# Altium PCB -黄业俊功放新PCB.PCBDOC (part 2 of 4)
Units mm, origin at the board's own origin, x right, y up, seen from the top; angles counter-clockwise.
Board outline 130 x 100.6 mm, 2 copper layers (Top Layer, Bottom Layer); 47 components, 24 nets, 117 pads, 4 vias.
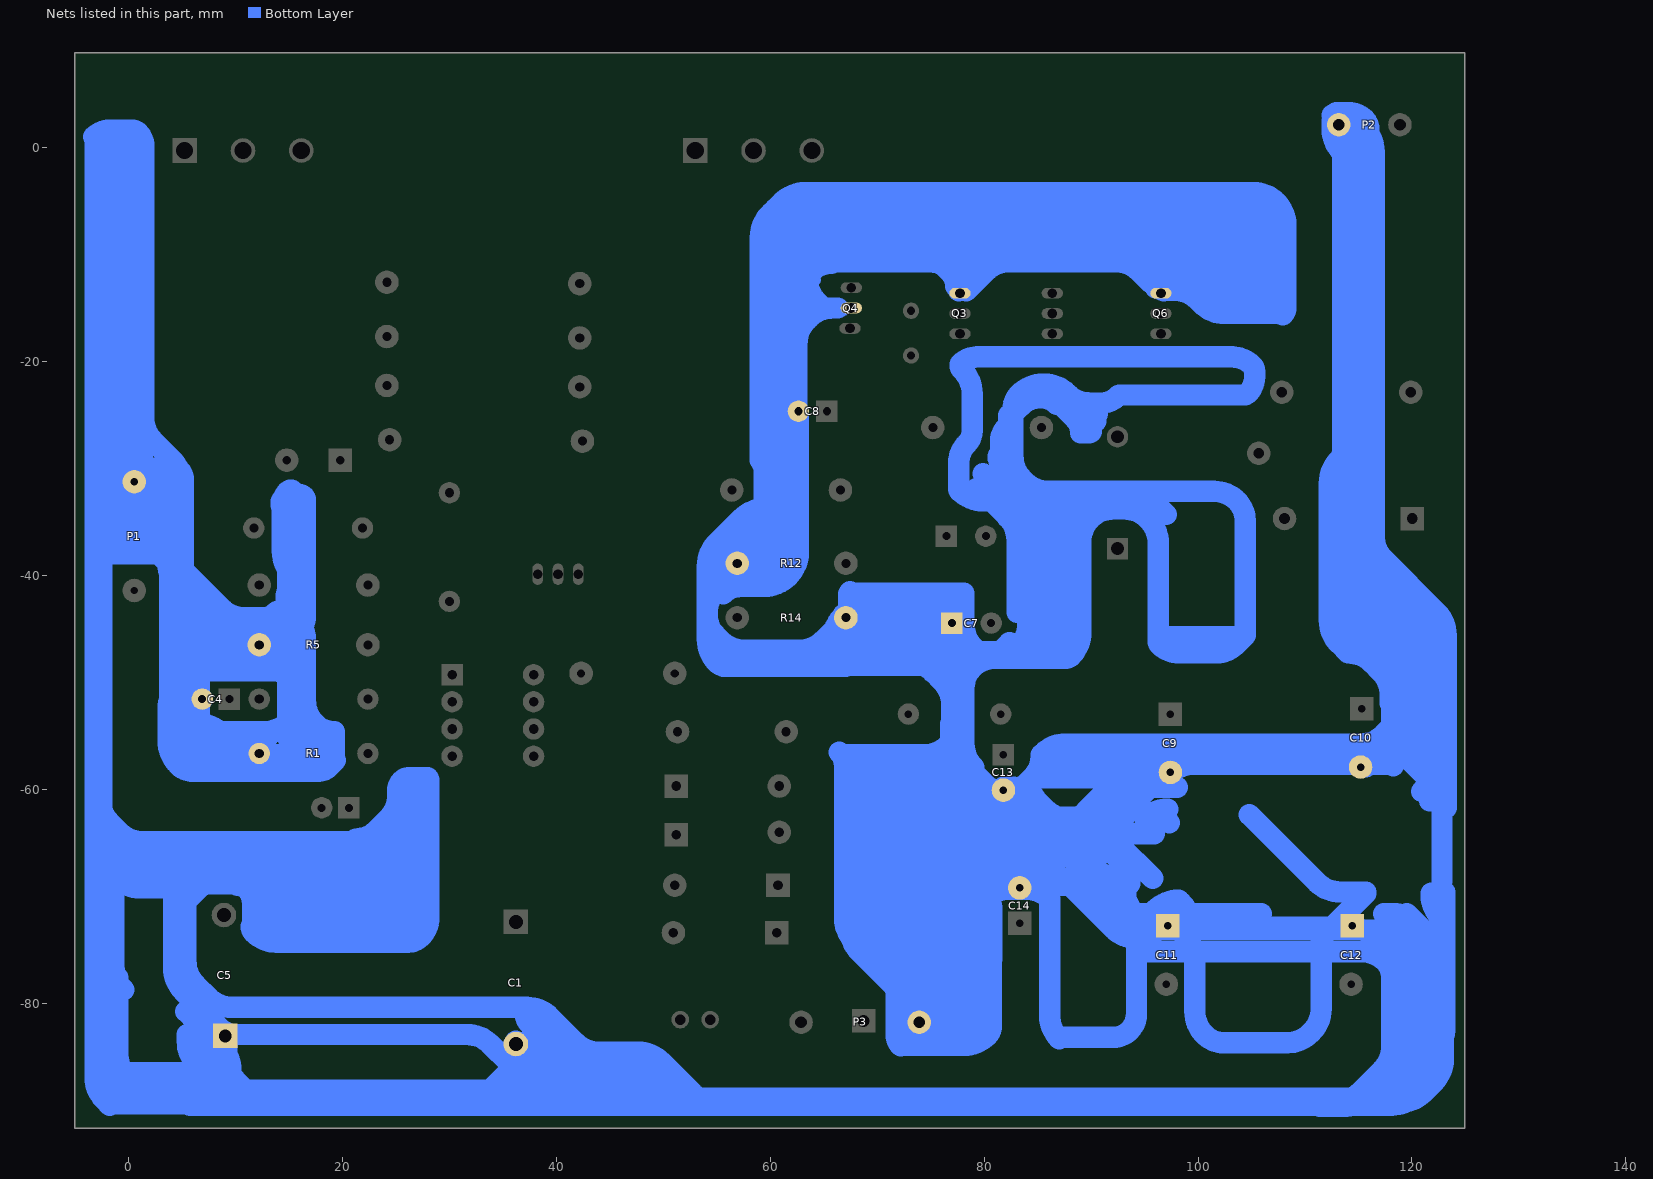
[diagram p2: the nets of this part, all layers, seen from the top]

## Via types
v1: diameter 2.54, hole 0.762, Top Layer to Bottom Layer, 4 vias

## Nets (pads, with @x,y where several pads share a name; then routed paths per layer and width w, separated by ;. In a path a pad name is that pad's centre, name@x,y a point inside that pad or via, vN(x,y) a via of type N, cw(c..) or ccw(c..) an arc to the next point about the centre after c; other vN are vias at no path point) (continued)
GND: (continued)
  Bottom Layer w2: -2.667,-58.42 -2.667,-60.96 ccw(c0.399,-60.96) -1.769,-63.128 -0.898,-63.999 ccw(c1.27,-61.831) 1.27,-64.897 24.892,-64.897 cw(c24.892,-67.963) 27.06,-65.795 cw(c25.549,-67.306) 27.686,-67.306 27.686,-71.628 cw(c24.62,-71.628) 26.788,-73.796 cw(c25.583,-72.591) 25.583,-74.295 13.843,-74.295 cw(c13.843,-71.229) 11.675,-73.397 cw(c12.266,-72.806) 11.43,-72.806 ccw(c11.43,-72.582) 11.588,-72.74 ccw(c10.742,-71.895) 11.938,-71.895 11.938,-70.367 ccw(c9.77,-70.367) 11.303,-68.834 7.682,-68.834 ccw(c7.682,-71.436) 5.842,-69.596 ccw(c7.068,-70.822) 5.334,-70.822 5.334,-76.073 ccw(c8.4,-76.073) 6.232,-78.241 7.484,-79.493 ccw(c9.652,-77.325) 9.652,-80.391 37.211,-80.391 cw(c37.211,-83.457) 39.379,-81.289 41.774,-83.684 ccw(c43.942,-81.516) 43.942,-84.582 47.625,-84.582 cw(c47.625,-87.648) 49.793,-85.48 52.696,-88.383 ccw(c54.864,-86.215) 54.864,-89.281 61.087,-89.281 ; -2.667,-39.624 -2.667,-32.233 cw(c-1.549,-32.233) -1.549,-31.115 P1.1@0.381,-31.115 ; -2.54,-51.816 -2.54,-33.831 ; -2.54,-47.244 -2.54,-88.29 ccw(c-1.422,-88.29) -1.422,-89.408 11.303,-89.408 ; -2.413,-80.391 -2.413,-85.623 ccw(c0.285,-85.623) -1.623,-87.531 -0.536,-88.618 ccw(c1.372,-86.71) 1.372,-89.408 8.382,-89.408 ; -2.413,-78.613 -2.413,-83.845 ccw(c0.285,-83.845) -1.623,-85.753 -0.028,-87.348 ccw(c1.88,-85.44) 1.88,-88.138 35.814,-88.138 ; -2.159,-64.516 -1.152,-65.523 ccw(c1.016,-63.355) 1.016,-66.421 24.003,-66.421 cw(c24.003,-69.487) 26.171,-67.319 ccw(c26.193,-67.341) 26.162,-67.341 26.162,-71.374 cw(c23.096,-71.374) 25.264,-73.542 ccw(c23.709,-75.097) 23.709,-72.898 14.794,-72.898 cw(c14.794,-70.296) 12.954,-72.136 cw(c13.261,-71.829) 12.827,-71.829 12.827,-70.358 ccw(c9.761,-70.358) 11.929,-68.19 ccw(c11.644,-68.475) 11.644,-68.072 1.143,-68.072 cw(c1.143,-65.006) -1.025,-67.174 -2.286,-65.913 ccw(c0.78,-65.913) -1.388,-68.081 -1.152,-68.317 ccw(c1.016,-66.149) 1.016,-69.215 5.588,-69.215 ; -1.905,0.762 -1.905,-30.703 ccw(c-0.604,-30.703) -1.524,-31.623 ; -1.778,-89.535 -2.277,-89.036 cw(c-0.109,-86.868) -3.175,-86.868 -3.175,0.709 ccw(c-3.609,0.709) -3.302,1.016 cw(c-1.769,-0.517) -1.769,1.651 0.276,1.651 cw(c0.276,0.784) 0.889,1.397 cw(c-0.337,0.171) 1.397,0.171 1.397,-25.273 ccw(c4.463,-25.273) 2.295,-27.441 4.07,-29.216 cw(c2.553,-30.734) 4.699,-30.734 ; -1.651,-1.524 -0.396,-0.269 ccw(c-1.047,0.381) -0.127,0.381 -0.127,-6.043 cw(c-0.561,-6.043) -0.254,-6.35 cw(c-0.561,-6.657) -0.127,-6.657 -0.127,-31.242 0.372,-30.743 ccw(c-1.796,-28.575) 1.27,-28.575 1.27,-27.283 ccw(c0.403,-27.283) 1.016,-26.67 ; -1.524,-37.211 1.168,-37.211 cw(c1.168,-39.909) 3.076,-38.001 3.274,-38.199 cw(c1.366,-40.107) 4.064,-40.107 4.064,-43.688 ; -1.397,-69.215 -1.397,-76.581 ccw(c1.669,-76.581) -0.499,-78.749 ; -1.016,-77.597 -1.016,-84.954 ccw(c1.152,-84.954) -0.381,-86.487 7.992,-86.487 cw(c7.992,-88.655) 9.525,-87.122 9.525,-86.233 ccw(c6.459,-86.233) 8.627,-84.065 5.334,-80.772 6.214,-81.652 cw(c4.046,-83.82) 7.112,-83.82 7.112,-86.487 6.359,-85.734 cw(c8.527,-83.566) 5.461,-83.566 5.461,-82.931 31.623,-82.931 cw(c31.623,-85.997) 33.791,-83.829 35.56,-85.598 ; 0.254,-30.099 2.741,-30.099 ccw(c2.741,-29.665) 3.048,-29.972 cw(c1.515,-31.505) 3.683,-31.505 3.683,-39.014 ccw(c6.381,-39.014) 4.473,-40.922 8.481,-44.93 ccw(c10.389,-43.022) 10.389,-45.72 R5.1@11.938,-45.72 ; 0.381,-36.322 ccw(c1.607,-35.096) 1.607,-36.83 1.651,-36.83 2.704,-37.883 ccw(c2.921,-37.666) 2.921,-37.973 ccw(c3.228,-37.973) 3.011,-38.19 3.959,-39.138 cw(c3.092,-40.005) 4.318,-40.005 ccw(c5.544,-40.005) 4.677,-40.872 4.699,-40.894 4.699,-42.164 cw(c4.392,-42.471) 4.826,-42.471 4.826,-53.492 ccw(c7.524,-53.492) 5.616,-55.4 6.068,-55.852 ccw(c7.976,-53.944) 7.976,-56.642 12.065,-56.642 8.738,-56.642 cw(c8.738,-53.944) 6.83,-55.852 cw(c7.681,-55) 6.477,-55 ; 0.635,-33.581 ccw(c0.201,-33.581) 0.508,-33.274 0.508,-34.491 ccw(c0.942,-34.491) 0.635,-34.798 ccw(c2.168,-36.331) 0,-36.331 0,-36.703 ccw(c0,-37.601) -0.635,-36.966 -0.694,-37.025 ccw(c-1.524,-37.855) -1.524,-36.681 cw(c-0.657,-36.681) -1.27,-36.068 ccw(c-2.496,-34.842) -0.762,-34.842 -0.762,-34.544 cw(c0.464,-34.544) -0.403,-33.677 1.143,-32.131 cw(c0.223,-33.051) 1.524,-33.051 1.524,-33.931 ccw(c2.391,-33.931) 1.778,-34.544 1.778,-35.941 cw(c1.778,-35.836) 1.704,-35.91 1.121,-35.328 cw(c0.635,-34.842) 0.635,-35.529 cw(c-0.285,-35.529) 0.366,-36.18 cw(c-0.285,-36.83) 0.635,-36.83 cw(c0.635,-38.67) 1.936,-37.369 2.286,-37.719 ccw(c0.446,-35.879) 3.048,-35.879 3.048,-31.242 ccw(c2.741,-31.549) 2.741,-31.115 1.118,-31.115 ccw(c1.118,-33.813) -0.79,-31.905 -1.496,-32.611 ccw(c0.412,-34.519) -2.286,-34.519 -2.286,-37.973 2.184,-37.973 cw(c2.184,-40.671) 4.092,-38.763 ; 2.413,-29.972 4.392,-29.972 cw(c4.392,-30.406) 4.699,-30.099 cw(c3.779,-31.019) 5.08,-31.019 5.08,-41.529 ; 2.54,-35.814 2.54,-35.839 ccw(c5.238,-35.839) 3.33,-37.747 ; 3.81,-50.038 3.81,-55.827 ccw(c4.244,-55.827) 3.937,-56.134 ccw(c5.47,-54.601) 5.47,-56.769 R1.2@11.684,-56.769 ; 3.81,-39.624 3.81,-53.111 ccw(c6.508,-53.111) 4.6,-55.019 5.56,-55.979 ccw(c7.468,-54.071) 7.468,-56.769 R1.2@12.065,-56.769 ; 4.191,-69.977 4.191,-76.708 ccw(c7.257,-76.708) 5.089,-78.876 C5.1@8.763,-82.55 ; 4.318,-35.56 4.318,-37.465 ccw(c7.384,-37.465) 5.216,-39.633 8.627,-43.044 ccw(c10.795,-40.876) 10.795,-43.942 14.649,-43.942 cw(c14.649,-45.676) 15.875,-44.45 cw(c14.342,-45.983) 16.51,-45.983 16.51,-51.689 ccw(c19.576,-51.689) 17.408,-53.857 ccw(c19.226,-52.039) 19.226,-54.61 19.226,-57.088 ccw(c19.493,-57.088) 19.304,-57.277 18.647,-57.934 cw(c17.78,-57.067) 17.78,-58.293 5.842,-58.293 cw(c5.842,-56.76) 4.758,-57.844 4.581,-57.667 cw(c6.749,-55.499) 3.683,-55.499 3.683,-54.356 3.683,-52.451 cw(c6.749,-52.451) 4.581,-50.283 5.452,-49.412 cw(c7.62,-51.58) 7.62,-48.514 12.967,-48.514 cw(c12.967,-51.549) 15.113,-49.403 cw(c14.193,-50.323) 15.494,-50.323 15.494,-52.451 ccw(c18.56,-52.451) 16.392,-54.619 17.653,-55.88 17.653,-56.178 cw(c15.919,-56.178) 17.145,-57.404 14.741,-57.404 cw(c14.741,-55.236) 13.208,-56.769 15.717,-56.769 ccw(c15.717,-55.468) 16.637,-56.388 cw(c16.944,-56.081) 16.51,-56.081 cw(c16.51,-54.421) 15.336,-55.595 14.097,-54.356 ccw(c14.097,-55.582) 13.23,-54.715 13.171,-54.774 ccw(c13.388,-54.991) 13.081,-54.991 12.88,-54.991 ccw(c12.88,-55.425) 12.573,-55.118 ccw(c12.266,-55.425) 12.266,-54.991 8.487,-54.991 cw(c8.487,-54.124) 7.874,-54.737 7.614,-54.477 ccw(c6.096,-55.994) 6.096,-53.848 6.477,-53.848 cw(c6.477,-56.914) 8.645,-54.746 cw(c8.973,-55.074) 8.973,-54.61 12.7,-54.61 ccw(c12.7,-51.544) 14.868,-53.712 cw(c14.89,-53.69) 14.859,-53.69 14.859,-49.71 ccw(c14.425,-49.71) 14.732,-49.403 ccw(c13.506,-50.629) 13.506,-48.895 7.8,-48.895 cw(c7.8,-48.461) 7.493,-48.768 7.738,-48.523 cw(c9.906,-50.691) 9.906,-47.625 14.447,-47.625 cw(c14.447,-48.926) 15.367,-48.006 ccw(c15.06,-47.699) 15.494,-47.699 15.494,-45.974 15.076,-45.556 ccw(c14.859,-45.773) 14.859,-45.466 13.896,-45.466 cw(c13.896,-45.032) 13.589,-45.339 cw(c11.443,-43.193) 11.443,-46.228 11.96,-46.228 cw(c11.96,-47.095) 12.573,-46.482 cw(c12.88,-46.789) 12.88,-46.355 14.933,-46.355 ccw(c14.933,-45.921) 15.24,-46.228 15.612,-45.856 ccw(c13.444,-43.688) 16.51,-43.688 16.51,-38.354 16.51,-33.782 16.51,-32.946 ccw(c16.076,-32.946) 16.383,-32.639 ccw(c15.77,-33.252) 15.77,-32.385 15.547,-32.385 ccw(c15.547,-32.819) 15.24,-32.512 cw(c14.933,-32.205) 14.933,-32.639 ccw(c14.933,-33.432) 14.373,-32.871 ccw(c14.732,-33.23) 14.224,-33.23 ccw(c14.942,-33.23) 14.434,-33.738 cw(c14.023,-34.15) 14.605,-34.15 14.605,-35.306 14.605,-36.904 ccw(c15.039,-36.904) 14.732,-37.211 14.732,-39.063 ccw(c15.166,-39.063) 14.859,-39.37 14.859,-41.529 ccw(c15.166,-41.836) 14.732,-41.836 14.732,-42.26 cw(c13.431,-42.26) 14.351,-43.18 14.224,-43.307 14.202,-43.307 ccw(c14.202,-44.174) 13.589,-43.561 cw(c12.669,-42.641) 12.669,-43.942 11.303,-43.942 7.905,-43.942 cw(c7.905,-42.641) 6.985,-43.561 6.709,-43.285 ccw(c5.842,-44.152) 5.842,-42.926 ; 4.346,-39.144 cw(c6.254,-37.236) 3.556,-37.236 3.556,-32.106 ccw(c0.858,-32.106) 2.766,-30.198 ccw(c2.221,-30.743) 2.221,-29.972 -1.927,-29.972 ccw(c-1.927,-30.839) -2.54,-30.226 ccw(c-1.927,-30.839) -2.794,-30.839 -2.794,-83.845 ccw(c-0.096,-83.845) -2.004,-85.753 0.099,-87.856 ccw(c2.007,-85.948) 2.007,-88.646 36.269,-88.646 ccw(c36.269,-88.212) 36.576,-88.519 ccw(c37.496,-87.599) 37.496,-88.9 118.262,-88.9 ccw(c118.262,-86.202) 120.17,-88.11 121.613,-86.667 ccw(c121.18,-86.233) 121.793,-86.233 121.793,-84.762 cw(c122.227,-84.762) 121.92,-84.455 121.92,-80.317 cw(c122.354,-80.317) 122.047,-80.01 122.047,-76.835 122.047,-75.057 122.047,-73.533 122.047,-83.337 cw(c119.349,-83.337) 121.257,-85.245 117.602,-88.9 ; 4.572,-70.739 ccw(c4.572,-69.513) 5.439,-70.38 9.017,-66.802 ; 4.572,-51.562 C4.2@6.858,-51.562 ; 4.572,-50.292 7.084,-47.78 ; 4.826,-53.34 ccw(c5.439,-53.34) 5.006,-53.774 6.068,-54.836 ccw(c7.976,-52.928) 7.976,-55.626 8.636,-55.626 ; 4.826,-50.673 6.551,-48.948 cw(c6.985,-49.381) 6.985,-48.768 ; 4.953,-46.228 R5.1@12.065,-46.228 ; 5.588,-89.408 7.899,-89.408 ccw(c7.899,-88.29) 9.017,-88.29 C5.1@9.017,-82.677 ; 5.588,-50.673 5.588,-51.714 ccw(c8.286,-51.714) 6.378,-53.622 8.227,-55.471 ccw(c10.135,-53.563) 10.135,-56.261 R1.2@11.938,-56.261 ; 5.588,-44.323 cw(c5.588,-44.63) 5.805,-44.413 6.195,-44.803 ccw(c8.103,-42.895) 8.103,-45.593 8.509,-45.593 ; 5.588,-42.418 8.608,-45.438 ccw(c10.516,-43.53) 10.516,-46.228 R5.1@11.811,-46.228 ; 5.715,-89.535 118.11,-89.535 ccw(c118.11,-86.469) 120.278,-88.637 121.403,-87.512 ccw(c119.235,-85.344) 122.301,-85.344 122.301,-74.23 cw(c124.903,-74.23) 123.063,-72.39 122.691,-72.018 cw(c124.859,-69.85) 121.793,-69.85 121.793,-69.723 ; 5.969,-88.646 8.227,-86.388 ccw(c6.319,-84.48) 9.017,-84.48 C5.1@9.017,-82.804 ; C4.2@5.969,-51.308 cw(c4.436,-52.841) 6.604,-52.841 6.604,-53.594 7.846,-54.836 ccw(c9.754,-52.928) 9.754,-55.626 11.43,-55.626 ; 6.604,-89.408 8.227,-87.785 ccw(c6.319,-85.877) 9.017,-85.877 C5.1@9.017,-83.185 ; 6.604,-55.403 cw(c6.508,-55.403) 6.576,-55.471 ccw(c8.484,-53.563) 8.484,-56.261 R1.2@11.811,-56.261 ; C4.2@6.604,-51.562 6.604,-54.811 ccw(c7.038,-54.811) 6.731,-55.118 ; C4.2@6.604,-51.308 6.604,-48.567 cw(c7.038,-48.567) 6.731,-48.26 ; 6.716,-47.386 ccw(c6.065,-46.736) 6.985,-46.736 ; 6.731,-55.143 ccw(c7.849,-55.143) 7.849,-56.261 R1.2@12.065,-56.261 ; 6.731,-48.768 6.731,-48.895 8.735,-46.891 cw(c10.643,-48.799) 10.643,-46.101 R5.1@11.684,-46.101 ; C5.1@9.017,-83.312 9.017,-85.75 ccw(c11.715,-85.75) 9.807,-87.658 11.684,-89.535 ; C5.1@9.144,-82.804 9.144,-85.242 ccw(c11.842,-85.242) 9.934,-87.15 11.594,-88.81 ccw(c11.811,-88.593) 11.811,-88.9 ; 10.16,-68.961 cw(c10.16,-70.187) 11.027,-69.32 cw(c9.748,-70.599) 11.557,-70.599 11.557,-72.39 ; R1.2@12.192,-56.769 R1.2@12.192,-55.753 ; 12.573,-68.072 24.301,-68.072 cw(c24.301,-69.806) 25.527,-68.58 25.527,-69.915 cw(c22.925,-69.915) 24.765,-71.755 15.757,-71.755 cw(c15.757,-69.587) 14.224,-71.12 14.224,-69.903 ccw(c13.79,-69.903) 14.097,-69.596 14.224,-69.469 14.605,-69.469 ccw(c16.138,-67.936) 16.138,-70.104 24.511,-70.104 23.832,-70.104 ccw(c23.832,-71.838) 22.606,-70.612 cw(c21.686,-69.692) 21.686,-70.993 ; 15.24,-43.561 15.24,-39.909 cw(c15.271,-39.909) 15.249,-39.887 cw(c17.417,-37.719) 14.351,-37.719 14.351,-33.283 cw(c15.906,-33.283) 14.806,-32.184 cw(c15.24,-32.617) 15.24,-32.004 ; 21.209,-64.643 ccw(c21.209,-61.884) 23.16,-63.835 24.248,-62.747 ccw(c22.08,-60.579) 25.146,-60.579 25.146,-60.102 cw(c26.447,-60.102) 25.527,-59.182 cw(c26.14,-59.795) 26.14,-58.928 27.94,-58.928 cw(c27.633,-59.235) 28.067,-59.235 28.067,-71.947 cw(c25.465,-71.947) 27.305,-73.787 cw(c26.079,-72.561) 26.079,-74.295 23.876,-74.295 cw(c23.876,-71.229) 21.708,-73.397 21.494,-73.183 cw(c22.795,-71.882) 20.955,-71.882 20.955,-68.961 cw(c24.021,-68.961) 21.853,-66.793 25.772,-62.874 ccw(c23.604,-60.706) 26.67,-60.706 26.67,-60.452 26.67,-62.834 ccw(c27.971,-62.834) 27.051,-63.754 26.76,-64.045 ccw(c26.977,-64.262) 26.67,-64.262 26.67,-64.389 ; 33.02,-88.9 35.151,-86.769 ccw(c33.243,-84.861) 35.941,-84.861 C1.2@35.941,-83.947 ; C1.2@36.195,-83.82 36.195,-89.228 ccw(c36.629,-89.228) 36.322,-89.535 ; C1.2@36.195,-83.566 36.195,-84.861 ccw(c38.893,-84.861) 36.985,-86.769 39.243,-89.027 ; 37.084,-81.026 ccw(c38.31,-81.026) 37.443,-81.893 40.885,-85.335 ccw(c43.053,-83.167) 43.053,-86.233 47.752,-86.233 cw(c47.752,-89.299) 49.92,-87.131 50.673,-87.884 42.799,-87.884 cw(c42.799,-84.818) 40.631,-86.986 37.211,-83.566 38.345,-84.7 cw(c36.177,-86.868) 39.243,-86.868 39.243,-88.646 38.363,-87.766 cw(c40.531,-85.598) 37.465,-85.598 ; 54.102,-45.085 ccw(c57.168,-45.085) 55,-47.253 55.109,-47.362 ccw(c57.277,-45.194) 57.277,-48.26 63.574,-48.26 ccw(c63.574,-47.826) 63.881,-48.133 cw(c64.494,-48.746) 64.494,-47.879 67.078,-47.879 ccw(c67.078,-47.012) 67.691,-47.625 ; 54.102,-44.704 54.102,-43.434 cw(c57.168,-43.434) 55,-41.266 55.109,-41.157 cw(c57.277,-43.325) 57.277,-40.259 60.307,-40.259 ccw(c60.307,-38.989) 61.205,-39.887 ccw(c59.037,-37.719) 62.103,-37.719 62.103,-31.877 ; 54.102,-43.815 ccw(c56.555,-43.815) 54.82,-45.549 55.363,-46.092 ccw(c57.531,-43.924) 57.531,-46.99 62.738,-46.99 ccw(c62.738,-43.924) 64.906,-46.092 66.793,-44.205 cw(c68.961,-46.373) 68.961,-43.307 75.587,-43.307 cw(c75.587,-44.174) 76.2,-43.561 cw(c75.893,-43.868) 76.327,-43.868 C7.1@76.327,-45.339 ; 54.102,-42.291 cw(c57.168,-42.291) 55,-40.123 55.722,-39.401 cw(c57.023,-40.702) R12.2@57.023,-38.862 ; 54.102,-41.91 54.102,-39.116 cw(c57.168,-39.116) 55,-36.948 57.268,-34.68 cw(c59.436,-36.848) 59.436,-33.782 59.436,-30.13 ccw(c58.135,-30.13) 59.055,-29.21 59.055,-19.641 cw(c60.789,-19.641) 59.563,-18.415 ; 54.229,-39.37 ccw(c54.536,-39.677) 54.102,-39.677 54.102,-45.987 ccw(c57.137,-45.987) 54.991,-48.133 ccw(c55.911,-47.213) 55.911,-48.514 67.056,-48.514 ; 54.414,-39.205 cw(c55.762,-40.903) 54.936,-38.899 cw(c55.762,-40.903) 55.762,-38.735 R12.2@56.007,-38.735 ; 55.245,-38.862 59.458,-34.649 ccw(c58.591,-33.782) 59.817,-33.782 ccw(c58.284,-32.249) 60.452,-32.249 60.452,-31.821 ccw(c58.748,-31.821) 59.953,-30.616 cw(c62.121,-28.448) 59.055,-28.448 59.055,-28.321 59.055,-8.382 cw(c62.121,-8.382) 59.953,-6.214 60.452,-5.715 ; 55.372,-41.145 ccw(c56.142,-41.145) 55.598,-41.689 cw(c57.211,-43.303) 57.211,-41.021 59.436,-41.021 ccw(c59.436,-37.955) 61.604,-40.123 61.713,-40.014 ccw(c59.545,-37.846) 62.611,-37.846 C8.2@62.611,-24.638 ; 55.753,-38.862 56.515,-38.862 ccw(c56.515,-35.796) 57.388,-38.735 ccw(c56.515,-35.796) 58.683,-37.964 60.316,-36.331 ccw(c58.148,-34.163) 61.214,-34.163 61.214,-14.605 ; R12.2@56.388,-38.735 58.674,-38.735 ccw(c58.674,-37.465) 59.856,-37.93 ; R12.2@56.769,-38.862 ccw(c56.769,-35.796) 57.642,-38.735 ccw(c56.769,-35.796) 58.937,-37.964 ccw(c56.813,-35.84) 59.534,-37.113 ccw(c56.813,-35.84) 59.817,-35.84 59.817,-11.049 cw(c62.883,-11.049) 60.071,-9.827 cw(c62.883,-11.049) 60.072,-9.824 ; R12.2@57.785,-38.735 ccw(c57.785,-35.669) 59.856,-37.93 ; 58.293,-48.387 75.946,-48.387 ; 59.182,-8.255 cw(c62.248,-8.255) 60.08,-6.087 61.078,-5.089 cw(c63.246,-7.257) 63.246,-4.191 105.182,-4.191 cw(c105.182,-7.195) 107.306,-5.071 cw(c105.138,-7.239) 108.204,-7.239 108.204,-11.303 ; 59.817,-39.878 60.839,-38.856 ccw(c59.322,-37.338) 61.468,-37.338 ; 59.817,-13.335 59.817,-8.509 cw(c62.883,-8.509) 60.715,-6.341 60.824,-6.232 cw(c62.992,-8.4) 62.992,-5.334 103.251,-5.334 cw(c103.251,-8.4) 105.419,-6.232 107.306,-8.119 cw(c105.138,-10.287) 108.204,-10.287 108.204,-13.282 108.204,-14.953 cw(c107.231,-14.953) 107.919,-15.641 ccw(c107.565,-15.995) 107.565,-15.494 102.489,-15.494 cw(c102.489,-12.428) 100.321,-14.596 99.958,-14.233 ccw(c97.79,-16.401) 97.79,-13.335 97.536,-13.335 cw(c97.536,-10.269) 95.368,-12.437 94.497,-11.566 ccw(c92.329,-13.734) 92.329,-10.668 82.296,-10.668 ccw(c82.296,-13.734) 80.128,-11.566 Q3.1@78.325,-13.369 ; 60.071,-26.67 ccw(c60.071,-26.416) 60.325,-26.416 ; 60.071,-9.902 cw(c62.208,-9.902) 60.072,-9.824 ; 60.288,-11.213 62.221,-9.28 cw(c64.389,-11.448) 62.473,-9.054 ; 61.214,-28.011 cw(c65.984,-28.011) C8.2@62.611,-24.638 ; 61.214,-21.265 ccw(c65.984,-21.265) C8.2@62.611,-24.638 ; 61.214,-16.383 62.162,-15.435 cw(c63.246,-16.519) 62.401,-15.24 cw(c63.246,-16.519) 63.246,-14.986 ; 61.468,-48.514 ccw(c61.468,-45.448) 62.341,-48.387 ccw(c61.468,-45.448) 62.69,-48.26 ccw(c61.468,-45.448) 63.636,-47.616 65.771,-45.481 ccw(c65.12,-44.831) 66.04,-44.831 ; 61.468,-6.985 cw(c63.308,-8.825) 63.308,-6.223 96.012,-6.223 ; 61.595,-16.764 61.595,-17.018 cw(c60.675,-17.938) 61.976,-17.938 61.976,-34.544 cw(c58.91,-34.544) 61.078,-36.712 59.953,-37.837 cw(c57.785,-35.669) 59.856,-37.93 ; 61.864,-10.907 62.602,-10.169 cw(c64.77,-12.337) 64.77,-9.271 ; 61.976,-26.171 cw(c64.144,-26.171) C8.2@62.611,-24.638 ; 61.976,-23.105 ccw(c64.144,-23.105) C8.2@62.611,-24.638 ; 61.976,-14.478 61.976,-13.694 ccw(c61.109,-13.694) 61.722,-13.081 61.722,-11.938 ccw(c62.029,-11.938) 61.812,-12.155 64.516,-14.859 ccw(c64.209,-15.166) 64.209,-14.732 64.135,-14.732 ccw(c62.909,-14.732) 64.101,-14.444 ccw(c62.909,-14.732) 63.776,-13.865 63.5,-13.589 cw(c63.807,-13.282) 63.373,-13.282 63.373,-12.446 cw(c64.599,-12.446) 63.732,-11.579 64.126,-11.185 cw(c66.294,-13.353) 64.555,-10.828 ; 62.103,-17.018 63.5,-15.621 ; C8.2@62.484,-24.257 62.484,-18.288 cw(c65.55,-18.288) 62.57,-17.569 cw(c65.55,-18.288) 63.382,-16.12 63.618,-15.884 cw(c65.786,-18.052) 64.564,-15.24 cw(c65.786,-18.052) 65.786,-14.986 ; 63.106,-7.874 ccw(c63.106,-10.909) 60.96,-8.763 61.512,-8.763 cw(c61.512,-10.497) 62.473,-9.054 ; 63.119,-10.033 76.064,-10.033 cw(c76.064,-12.201) 76.665,-10.118 ; 63.364,-11.566 cw(c65.532,-13.734) 64.555,-10.828 ; 63.364,-11.185 cw(c65.532,-13.353) 64.443,-10.487 cw(c65.532,-13.353) 64.978,-10.337 ; 63.491,-11.312 cw(c65.659,-13.48) 64.075,-10.855 cw(c65.659,-13.48) 65.163,-10.454 ; 63.68,-11.25 64.77,-10.16 ccw(c65.996,-8.934) 64.978,-10.337 ; 63.754,-14.986 66.294,-14.986 ; 63.89,-11.548 cw(c65.708,-13.366) 65.708,-10.795 ; 65.913,-8.382 64.389,-8.382 ccw(c64.389,-11.448) 62.473,-9.054 ; 65.996,-10.668 cw(c65.996,-8.934) 65.216,-10.483 ; 66.167,-46.33 cw(c69.444,-46.33) 67.127,-44.013 cw(c69.137,-46.023) 69.137,-43.18 ; 66.167,-45.292 cw(c67.483,-45.292) R14.2@67.086,-44.037 ; 66.294,-48.387 cw(c66.294,-48.26) 66.167,-48.26 66.167,-44.958 cw(c67.437,-44.958) 67.437,-43.688 74.676,-43.688 cw(c74.676,-44.958) 75.23,-43.815 cw(c74.676,-44.958) 75.946,-44.958 75.946,-45.847 cw(c74.676,-45.847) 75.912,-46.138 ; 66.294,-10.287 ccw(c66.294,-13.353) 65.379,-10.427 ; R14.2@66.802,-43.688 cw(c68.028,-44.914) 68.028,-43.18 77.089,-43.18 cw(c76.782,-43.487) 77.216,-43.487 77.216,-46.736 ; R14.2@66.929,-43.815 75.819,-43.815 ; R14.2@67.31,-43.688 67.31,-41.836 cw(c67.744,-41.836) 67.437,-41.529 ccw(c67.744,-41.222) 67.744,-41.656 78.105,-41.656 78.105,-44.577 ccw(c81.171,-44.577) 79.003,-46.745 79.629,-47.371 ; R14.2@67.437,-44.704 73.787,-44.704 cw(c73.787,-45.339) 74.42,-45.294 ; 68.199,-74.168 cw(c68.199,-74.475) 68.416,-74.258 73.143,-78.985 cw(c70.975,-81.153) 74.041,-81.153 P3.2@74.041,-81.788 ; 68.335,-70.621 cw(c70.503,-68.453) 67.437,-68.453 67.437,-67.31 67.437,-73.025 ccw(c70.503,-73.025) 68.335,-75.193 72.762,-79.62 cw(c70.594,-81.788) P3.2@73.66,-81.788 ; 68.58,-48.133 73.025,-48.133 cw(c73.025,-51.199) 74.247,-48.387 cw(c73.025,-51.199) 75.193,-49.031 76.064,-49.902 cw(c73.896,-52.07) 76.962,-52.07 ; 68.58,-47.117 cw(c68.58,-45.847) 67.564,-46.609 ; 68.961,-10.287 65.532,-10.287 ccw(c65.532,-13.353) 64.978,-10.337 ; 69.088,-74.168 69.596,-74.168 cw(c69.596,-77.234) 71.764,-75.066 73.016,-76.318 cw(c70.848,-78.486) 73.914,-78.486 73.914,-82.169 78.889,-82.169 ccw(c78.889,-81.302) 79.502,-81.915 79.747,-81.67 ccw(c77.579,-79.502) 80.645,-79.502 80.645,-75.565 80.608,-75.528 cw(c80.825,-75.311) 80.518,-75.311 ccw(c80.518,-77.457) 79,-75.94 76.336,-78.604 ccw(c78.504,-80.772) 75.438,-80.772 78.022,-80.772 ccw(c78.022,-79.038) 79.248,-80.264 ccw(c78.022,-79.038) 79.756,-79.038 79.756,-77.965 ccw(c76.721,-77.965) 78.867,-75.819 cw(c77.641,-74.593) 77.641,-76.327 ccw(c77.641,-77.045) 77.133,-76.537 75.147,-78.523 cw(c74.93,-78.306) 74.93,-78.613 74.93,-77.733 ccw(c72.762,-77.733) 74.295,-76.2 cw(c74.602,-76.2) 74.385,-75.983 78.83,-80.428 cw(c78.74,-80.518) 78.867,-80.518 78.867,-78.793 ccw(c78.433,-78.793) 78.74,-78.486 cw(c79.66,-77.566) 78.359,-77.566 78.359,-76.962 77.718,-76.321 cw(c79.235,-74.803) 77.089,-74.803 76.962,-74.803 cw(c76.962,-71.737) 74.794,-73.905 73.019,-72.13 ccw(c71.501,-73.647) 71.501,-71.501 ; 69.137,-44.704 cw(c69.137,-41.861) 67.127,-43.871 ccw(c71.896,-39.102) 71.896,-45.847 ; 70.104,-9.271 74.549,-9.271 cw(c74.549,-12.337) 76.665,-10.118 ; 71.12,-10.414 65.659,-10.414 ccw(c65.659,-13.48) 65.379,-10.427 ; 71.12,-9.525 73.406,-9.525 cw(c73.406,-12.591) 75.043,-9.999 ; 71.247,-77.978 cw(c70.021,-79.204) 71.755,-79.204 71.755,-82.961 ccw(c73.2,-82.961) 72.178,-83.983 cw(c72.265,-84.07) 72.265,-83.947 78.105,-83.947 ccw(c78.105,-80.881) 80.273,-83.049 ccw(c79.375,-82.151) 80.645,-82.151 80.645,-74.676 74.304,-81.017 ccw(c76.472,-83.185) 73.406,-83.185 ; 72.127,-10.668 ccw(c72.127,-8.5) 73.66,-10.033 ; 72.136,-66.802 cw(c72.136,-66.495) 71.919,-66.712 71.628,-66.421 cw(c71.935,-66.114) 71.501,-66.114 71.501,-65.383 ccw(c70.634,-65.383) 71.247,-64.77 ccw(c70.984,-64.507) 71.356,-64.507 71.356,-64.389 cw(c71.356,-65.659) 72.254,-64.761 cw(c70.086,-66.929) 73.152,-66.929 ; 72.263,-44.958 73.025,-44.958 cw(c73.025,-48.024) 74.42,-45.294 ; 73.152,-47.117 ccw(c73.152,-45.847) 74.422,-45.847 74.422,-45.339 ccw(c73.787,-45.339) 74.42,-45.294 ; 73.45,-75.99 72.526,-75.066 ccw(c70.358,-77.234) 70.358,-74.168 67.818,-74.168 cw(c69.964,-72.022) 66.929,-72.022 66.929,-57.741 ccw(c65.195,-57.741) 66.421,-56.515 ccw(c67.034,-55.902) 67.034,-56.769 74.422,-56.769 ccw(c74.422,-53.703) 76.59,-55.871 76.64,-55.821 ccw(c75.556,-54.737) 77.089,-54.737 ; 73.896,-43.18 cw(c73.896,-47.516) C7.1@76.962,-44.45 ; 74.041,-9.906 74.295,-9.906 cw(c74.295,-12.972) 75.043,-9.999 ; 74.676,-44.958 cw(c73.787,-44.958) 74.571,-45.377 ; 74.803,-10.668 cw(c74.803,-13.734) 76.113,-10.962 cw(c74.803,-13.734) 76.971,-11.566 77.507,-12.102 cw(c77.29,-12.319) 77.589,-12.249 ; 74.921,-43.18 cw(c74.921,-45.348) 76.454,-43.815 cw(c75.228,-45.041) C7.1@76.764,-44.236 ; 75.429,-43.815 cw(c75.429,-45.983) C7.1@76.962,-44.45 ; 75.63,-46.101 cw(c75.63,-47.179) 75.912,-46.138 ; 75.692,-76.585 75.692,-69.85 cw(c78.758,-69.85) 76.59,-67.682 76.953,-67.319 ccw(c74.785,-65.151) 77.851,-65.151 77.851,-64.389 cw(c80.917,-64.389) 78.749,-62.221 75.314,-58.786 cw(c75.933,-58.166) 75.057,-58.166 ccw(c74.137,-59.086) 74.137,-57.785 68.326,-57.785 ccw(c68.939,-58.398) 68.072,-58.398 68.072,-65.606 ccw(c68.506,-65.606) 68.199,-65.913 cw(c67.586,-66.526) 68.453,-66.526 68.453,-71.82 ccw(c71.055,-71.82) 69.215,-73.66 71.628,-73.66 cw(c71.628,-76.726) 73.796,-74.558 73.988,-74.75 ccw(c74.422,-74.317) 74.422,-74.93 74.422,-71.256 ccw(c72.254,-71.256) 73.787,-69.723 73.787,-68.484 cw(c75.088,-68.484) 74.168,-67.564 74.407,-67.803 ccw(c75.057,-67.152) 75.057,-68.072 cw(c77.51,-68.072) 75.775,-66.338 76.73,-65.383 ccw(c75.863,-64.516) 77.089,-64.516 77.789,-64.516 cw(c77.789,-67.118) 79.629,-65.278 82.414,-68.063 ccw(c84.582,-65.895) 84.582,-68.961 87.757,-68.961 82.565,-63.769 ccw(c81.915,-64.42) 81.915,-63.5 83.947,-63.5 cw(c83.947,-66.566) 86.115,-64.398 95.631,-73.914 94.234,-73.914 cw(c94.234,-70.848) 92.066,-73.016 87.376,-68.326 84.328,-68.326 cw(c84.328,-65.26) 82.16,-67.428 75.447,-60.715 ccw(c73.279,-62.883) 73.279,-59.817 cw(c73.279,-58.591) 72.412,-59.458 cw(c73.691,-60.737) 73.691,-58.928 cw(c73.691,-58.24) 73.205,-58.727 cw(c71.799,-57.321) 71.799,-59.309 69.014,-59.309 cw(c69.014,-58.875) 68.707,-59.182 ccw(c69.627,-58.262) 69.627,-59.563 cw(c69.627,-61.635) 71.092,-60.17 73.778,-62.856 ccw(c75.946,-60.688) 75.946,-63.754 ccw(c74.106,-63.754) 75.407,-62.453 74.437,-61.483 ccw(c73.787,-62.134) 73.787,-61.214 cw(c73.787,-60.907) 73.57,-61.124 ccw(c72.867,-61.827) 72.867,-60.833 70.612,-60.833 69.395,-60.833 ccw(c69.395,-61.267) 69.088,-60.96 69.088,-69.736 ccw(c72.123,-69.736) 69.977,-71.882 70.776,-72.681 cw(c70.559,-72.898) 70.866,-72.898 73.301,-72.898 cw(c73.301,-73.765) 73.914,-73.152 70.739,-69.977 70.612,-69.85 70.612,-62.716 ccw(c69.745,-62.716) 70.358,-62.103 72.254,-63.999 ccw(c74.422,-61.831) 74.422,-64.897 75.565,-64.897 73.802,-66.66 cw(c73.152,-66.009) 73.152,-66.929 ; 75.819,-57.023 75.819,-59.734 ccw(c77.553,-59.734) 76.327,-60.96 ; 75.819,-48.387 ccw(c75.819,-47.117) 76.962,-47.671 ccw(c75.819,-47.117) 77.089,-47.117 77.089,-45.085 ccw(c75.819,-45.085) 76.962,-44.531 ccw(c75.819,-45.085) C7.1@76.764,-44.236 ; 75.946,-46.177 cw(c77.922,-46.177) C7.1@76.962,-44.45 ; 75.946,-45.586 cw(c77.089,-45.586) C7.1@76.962,-44.45 ; 76.2,-46.99 ccw(c75.893,-46.99) 76.11,-46.773 75.193,-45.856 ccw(c73.025,-48.024) 74.571,-45.377 ; 76.463,-10.804 ccw(c74.295,-12.972) 76.318,-10.668 ccw(c74.295,-12.972) 75.168,-10.033 ccw(c74.295,-12.972) 75.043,-9.999 ; 76.835,-53.848 76.835,-56.896 ccw(c79.901,-56.896) 77.733,-59.064 78.985,-60.316 cw(c76.817,-62.484) 79.883,-62.484 79.883,-65.151 cw(c76.817,-65.151) 78.985,-67.319 77.987,-68.317 ccw(c80.155,-70.485) 77.089,-70.485 77.089,-77.47 ; 76.962,-10.668 65.532,-10.668 ccw(c65.532,-13.734) 64.555,-10.828 ; C7.1@77.089,-43.942 77.089,-44.323 ccw(c80.155,-44.323) 77.987,-46.491 ccw(c79.498,-44.98) 79.498,-47.117 81.779,-47.117 ccw(c81.779,-44.949) 83.312,-46.482 ccw(c81.472,-44.642) 84.074,-44.642 84.074,-36.957 ccw(c81.008,-36.957) 83.176,-34.789 82.305,-33.918 ccw(c80.137,-36.086) 80.137,-33.02 79.883,-33.02 cw(c79.883,-29.954) 77.715,-32.122 cw(c78,-31.837) 77.597,-31.837 77.597,-29.526 cw(c80.199,-29.526) 78.359,-27.686 ccw(c77.133,-26.46) 78.867,-26.46 78.867,-22.987 ccw(c75.801,-22.987) 77.969,-20.819 cw(c78.56,-20.228) 77.724,-20.228 cw(c79.34,-21.844) 79.34,-19.558 103.189,-19.558 cw(c103.189,-22.16) 105.029,-20.32 cw(c104.416,-20.933) 105.283,-20.933 105.283,-21.42 cw(c103.115,-21.42) 104.648,-22.953 cw(c104.258,-22.563) 104.258,-23.114 92.763,-23.114 ccw(c92.763,-23.548) 92.456,-23.241 cw(c90.923,-21.708) 90.923,-23.876 89.916,-23.876 cw(c89.916,-20.81) 87.748,-22.978 ccw(c85.624,-25.102) 85.624,-22.098 85.471,-22.098 ccw(c85.471,-25.164) 83.303,-22.996 ccw(c84.814,-24.507) 82.677,-24.507 82.677,-28.829 ccw(c85.743,-28.829) 83.575,-30.997 83.811,-31.233 ccw(c85.979,-29.065) 85.979,-32.131 101.473,-32.131 cw(c101.473,-35.197) 103.641,-33.029 cw(c101.823,-34.847) 104.394,-34.847 104.394,-45.593 103.461,-46.526 cw(c101.727,-44.791) 101.727,-47.244 98.233,-47.244 cw(c98.233,-44.642) 96.393,-46.482 cw(c96.7,-46.175) 96.266,-46.175 96.266,-36.957 ccw(c93.2,-36.957) 95.368,-34.789 95.259,-34.68 ccw(c93.091,-36.848) 93.091,-33.782 92.075,-33.782 ccw(c92.075,-36.848) 89.907,-34.68 ccw(c92.031,-36.804) 89.027,-36.804 89.027,-45.339 cw(c85.961,-45.339) 88.129,-47.507 cw(c87.538,-46.916) 87.538,-47.752 81.026,-47.752 ccw(c81.026,-50.818) 78.858,-48.65 ccw(c80.676,-50.468) 78.105,-50.468 78.105,-55.753 ccw(c81.171,-55.753) 79.003,-57.921 79.03,-57.948 ; 77.343,-12.573 77.343,-11.68 ccw(c75.206,-11.68) 76.717,-10.169 ccw(c74.549,-12.337) 76.665,-10.118 ; 77.47,-12.954 cw(c79.616,-12.954) 77.589,-12.249 ; Q3.1@77.597,-13.367 77.597,-11.176 ; 77.597,-12.319 ccw(c77.29,-12.319) 77.589,-12.249 ; 77.724,-12.954 cw(c80.177,-12.954) 78.251,-11.434 ; 77.978,-72.898 77.978,-71.984 cw(c80.676,-71.984) 78.768,-70.076 78.966,-69.878 cw(c80.874,-71.786) 80.874,-69.088 C14.2@82.804,-69.088 ; 77.978,-69.85 78.858,-68.97 cw(c81.026,-71.138) 81.026,-68.072 ; 77.978,-57.531 80.763,-60.316 cw(c78.595,-62.484) C13.2@81.251,-60.953 ; 77.978,-12.827 77.978,-12.7 cw(c81.044,-12.7) 78.251,-11.434 ; 78.099,-11.436 ccw(c79.616,-12.954) 77.597,-12.227 ccw(c79.616,-12.954) 77.589,-12.249 ; 78.105,-76.581 78.105,-70.866 cw(c81.171,-70.866) 78.232,-69.993 cw(c81.171,-70.866) 78.546,-69.282 cw(c81.171,-70.866) 79.003,-68.698 80.509,-67.192 cw(c82.677,-69.36) 81.915,-66.39 cw(c82.677,-69.36) 82.677,-66.294 89.802,-66.294 ccw(c89.802,-63.259) 91.679,-65.644 ccw(c89.802,-63.259) 91.948,-65.405 ; 78.105,-71.374 ccw(c77.798,-71.067) 78.232,-71.067 78.232,-69.977 cw(c80.378,-69.977) 78.274,-69.554 cw(c80.378,-69.977) 78.861,-68.459 80.763,-66.557 ccw(c78.595,-64.389) 81.661,-64.389 81.661,-62.484 ccw(c78.595,-62.484) C13.2@81.251,-60.953 ; 78.613,-47.625 77.65,-47.625 ; 79.121,-75.184 79.121,-70.612 ; 79.248,-31.877 80.518,-31.877 cw(c80.518,-34.943) 82.686,-32.775 85.852,-35.941 85.613,-36.18 ccw(c86.264,-36.83) 85.344,-36.83 ; 79.756,-32.004 79.756,-32.131 82.16,-34.535 cw(c79.992,-36.703) 83.058,-36.703 83.058,-43.434 ; 79.883,-59.436 ccw(c81.788,-57.531) C13.2@81.788,-60.225 ; 79.966,-10.077 cw(c77.798,-7.909) 79.788,-10.241 ; 80.137,-7.493 62.865,-7.493 ccw(c62.865,-10.559) 60.697,-8.391 ccw(c62.208,-9.902) 60.072,-9.824 ; 80.264,-8.001 82.931,-8.001 ; 80.645,-47.371 ccw(c80.645,-45.838) 81.729,-46.922 82.35,-46.301 ccw(c82.313,-46.264) 82.366,-46.264 ; 80.712,-75.879 80.712,-71.127 ccw(c79.981,-71.127) 80.498,-70.61 80.128,-70.24 cw(c82.296,-72.408) 82.296,-69.342 C14.2@83.947,-69.342 ; 80.899,-7.874 62.992,-7.874 ccw(c62.992,-10.94) 60.824,-8.772 60.715,-8.881 ccw(c62.883,-11.049) 60.072,-9.824 ; C13.2@80.918,-60.344 cw(c80.045,-61.218) 80.919,-60.345 cw(c80.045,-61.218) C13.2@81.251,-60.953 ; 81.28,-61.218 ccw(c80.045,-61.218) C13.2@81.251,-60.953 ; C13.2@81.407,-60.706 C13.2@81.407,-60.325 ; C13.2@81.534,-60.96 77.86,-57.286 cw(c80.028,-55.118) 76.962,-55.118 C7.1@76.962,-44.45 ; 81.661,-7.747 78.876,-10.532 ccw(c81.044,-12.7) 78.582,-10.873 ; C13.2@81.788,-60.425 cw(c81.788,-65.265) 85.211,-61.843 ; C13.2@81.788,-59.944 85.081,-63.237 ccw(c87.249,-61.069) 85.559,-63.627 ccw(c87.249,-61.069) 85.907,-63.826 ccw(c87.249,-61.069) 87.249,-64.135 95.885,-64.135 ; C13.2@81.788,-59.817 82.742,-59.817 cw(c82.742,-62.419) 84.039,-60.163 cw(c82.742,-62.419) 84.582,-60.579 cw(c83.969,-61.192) 84.79,-60.914 cw(c83.969,-61.192) 84.836,-61.192 ; C13.2@81.808,-60.423 cw(c82.431,-63.492) 84.645,-61.277 ; 81.915,-67.546 ccw(c83.457,-67.546) 82.367,-68.636 ; C13.2@82.042,-60.325 82.423,-60.325 cw(c82.423,-63.391) 84.591,-61.223 ; 82.209,-68.757 ccw(c81.026,-69.437) 81.026,-68.072 ; 82.225,-68.636 ccw(c80.215,-66.626) 83.058,-66.626 ; 82.244,-68.621 ccw(c81.38,-67.183) 83.058,-67.183 ; 82.296,-68.607 ccw(c82.296,-66.219) 83.984,-67.908 ; 82.307,-68.608 ccw(c82.502,-66.754) 83.82,-68.072 86.859,-65.033 cw(c89.027,-67.201) 87.805,-64.389 cw(c89.027,-67.201) 89.027,-64.135 ; 82.804,-9.779 81.534,-9.779 ccw(c81.534,-12.845) 80.085,-10.143 ; 82.931,-68.072 81.026,-68.072 ; 83.439,-66.167 87.757,-66.167 cw(c87.757,-69.233) 88.63,-66.294 cw(c87.757,-69.233) 89.925,-67.065 93.24,-70.38 cw(c92.373,-71.247) 93.599,-71.247 ; 83.439,-64.135 cw(c82.826,-64.748) 83.693,-64.748 83.693,-65.65 cw(c81.525,-65.65) 83.654,-66.058 ; 83.693,-60.325 85.589,-62.221 ccw(c87.757,-60.053) 85.874,-62.472 ; C14.2@83.82,-69.342 C14.2@83.947,-69.342 ; 83.82,-33.02 86.233,-33.02 cw(c86.233,-36.086) 88.401,-33.918 89.154,-34.671 ; 83.947,-60.071 85.716,-61.84 ccw(c87.884,-59.672) 86.969,-62.598 ; 83.947,-32.512 cw(c83.947,-33.738) 84.814,-32.871 87.503,-35.56 ; 84.074,-61.214 85.208,-62.348 ccw(c87.376,-60.18) 85.896,-62.865 ccw(c87.376,-60.18) 86.503,-63.119 ccw(c87.376,-60.18) 86.931,-63.213 ; 84.074,-46.482 85.217,-46.482 ccw(c85.217,-43.416) 87.385,-45.584 ccw(c86.487,-44.686) 87.757,-44.686 87.757,-39.751 ccw(c87.144,-39.138) 88.011,-39.138 88.011,-37.973 cw(c88.011,-37.666) 87.794,-37.883 ccw(c86.785,-38.893) 86.785,-37.465 86.211,-37.465 ccw(c86.211,-38.332) 85.598,-37.719 ccw(c86.211,-38.332) 85.344,-38.332 85.536,-38.332 cw(c85.536,-40.575) 87.122,-38.989 87.085,-39.026 cw(c86.868,-38.809) 86.868,-39.116 cw(c86.255,-39.116) 86.688,-39.55 ccw(c88.094,-40.956) 86.106,-40.956 86.106,-43.942 85.524,-44.524 ccw(c85.957,-44.958) 85.344,-44.958 cw(c85.344,-45.878) 85.994,-45.227 86.121,-45.1 ccw(c85.852,-44.831) 86.233,-44.831 86.233,-42.291 cw(c87.766,-40.758) 85.598,-40.758 ccw(c85.313,-40.758) 85.515,-40.557 84.836,-39.878 84.836,-43.075 ccw(c85.703,-43.075) 85.09,-43.688 85.127,-43.651 ccw(c84.91,-43.434) 85.217,-43.434 85.217,-40.798 cw(c86.518,-40.798) 85.598,-39.878 ; 84.201,-60.706 85.335,-61.84 ccw(c87.503,-59.672) 86.006,-62.348 ; 84.328,-61.214 84.954,-61.84 ccw(c87.122,-59.672) 85.874,-62.472 ; 84.455,-34.163 cw(c84.455,-32.017) 82.937,-33.534 79.883,-30.48 ccw(c81.723,-28.64) 81.723,-31.242 82.677,-31.242 ccw(c81.144,-31.242) 82.228,-30.158 81.549,-29.479 cw(c82.2,-28.829) 81.28,-28.829 ccw(c80.667,-28.216) 81.534,-28.216 81.534,-27.388 cw(c83.268,-27.388) 82.042,-26.162 ccw(c81.429,-25.549) 82.296,-25.549 82.296,-25.019 ccw(c82.296,-24.406) 82.73,-24.839 83.185,-24.384 83.452,-24.117 cw(c85.26,-25.924) 85.26,-23.368 cw(c85.26,-25.536) 86.793,-24.003 87.122,-24.003 cw(c87.122,-24.923) 87.772,-24.272 88.08,-24.58 ccw(c88.22,-24.439) 88.22,-24.638 cw(c88.22,-27.704) 90.388,-25.536 90.424,-25.572 90.424,-25.199 cw(c90.858,-25.199) 90.551,-24.892 ccw(c90.338,-25.105) 90.338,-24.804 89.281,-24.804 ccw(c91.745,-24.804) 90.003,-26.547 cw(c89.705,-26.248) 89.705,-26.67 89.027,-26.67 ccw(c87.187,-26.67) 88.488,-25.369 87.258,-24.139 ccw(c85.09,-26.307) 85.09,-23.241 ; 85.081,-61.713 ccw(c87.249,-59.545) 86.006,-62.348 ; 85.09,-64.389 89.154,-64.389 cw(c89.154,-67.455) 89.281,-64.392 ; 85.217,-58.928 91.812,-58.928 cw(c91.812,-61.096) 93.345,-59.563 ; 85.344,-63.627 91.821,-63.627 ccw(c91.821,-62.357) 93.091,-62.357 93.091,-58.547 cw(c93.98,-58.547) 93.097,-58.444 ; 85.725,-57.658 93.24,-57.658 cw(c93.24,-58.525) 93.853,-57.912 ; 85.852,-37.719 89.706,-33.865 cw(c91.44,-35.6) 91.44,-33.147 ; 86.106,-63.627 83.798,-65.935 cw(c82.931,-65.068) 83.654,-66.058 ; 87.457,-62.738 ccw(c88.011,-63.881) 87.249,-62.865 ccw(c88.011,-63.881) 87.06,-63.039 ; 87.503,-62.738 cw(c87.503,-59.672) 87.458,-62.738 ; 87.757,-63.119 cw(c87.757,-60.053) 87.06,-63.039 ; 88.011,-62.611 ccw(c88.011,-63.881) 87.508,-62.715 ; 88.392,-62.611 ccw(c88.392,-59.545) 88.711,-62.594 ; 88.519,-68.072 89.306,-68.072 cw(c89.306,-70.77) 91.214,-68.862 94.206,-71.854 ccw(c96.114,-69.946) 96.114,-72.644 C11.1@97.282,-72.644 ; 89.154,-62.738 ccw(c89.154,-59.672) 90.027,-62.611 ccw(c89.154,-59.672) 90.302,-62.515 ; 89.408,-64.389 ccw(c89.408,-67.455) 89.281,-64.392 ; 89.408,-63.881 89.916,-63.881 cw(c89.916,-66.947) 91.138,-64.135 cw(c89.916,-66.947) 91.186,-64.157 ; 89.789,-9.906 92.99,-9.906 cw(c92.99,-12.91) 93.854,-10.033 ; 90.297,-64.135 cw(c90.297,-67.201) 91.198,-64.27 ; 90.424,-63.627 ccw(c90.424,-60.561) 92.592,-62.729 C9.2@97.409,-57.912 ; 90.424,-63.119 ccw(c90.424,-61.849) 90.821,-63.055 ; 91.186,-67.945 ccw(c92.106,-67.945) 91.455,-68.595 ; 91.186,-64.008 91.186,-64.135 ccw(c91.948,-64.135) 91.186,-64.157 ; 91.567,-68.097 ccw(c94.265,-68.097) 91.66,-68.8 ccw(c94.265,-68.097) 92.357,-70.005 ; 91.948,-69.723 94.479,-72.254 ccw(c96.647,-70.086) 96.647,-73.152 117.466,-73.152 cw(c117.466,-75.32) 118.999,-73.787 119.625,-74.413 cw(c117.457,-76.581) 120.523,-76.581 120.523,-82.677 cw(c117.457,-82.677) 119.625,-84.845 115.706,-88.764 cw(c113.538,-86.596) 113.538,-89.662 111.379,-89.662 ; 92.084,-64.779 ccw(c89.916,-66.947) 91.802,-64.53 ; 92.71,-32.131 93.599,-32.131 cw(c93.599,-35.197) 95.767,-33.029 97.028,-34.29 ; 93.599,-68.834 ccw(c90.533,-68.834) 93.218,-67.354 ccw(c90.533,-68.834) 92.701,-66.666 91.322,-65.287 ccw(c89.154,-67.455) 89.281,-64.392 ; 93.614,-59.421 ccw(c94.265,-60.071) 93.398,-59.764 ccw(c94.265,-60.071) 93.354,-59.944 ccw(c94.265,-60.071) 93.345,-60.071 91.068,-62.348 cw(c88.9,-60.18) 90.867,-62.532 ; 93.726,-59.944 92.964,-59.944 ccw(c92.964,-63.01) 92.243,-60.03 ccw(c92.964,-63.01) 90.796,-60.842 89.618,-62.02 cw(c87.884,-60.285) 89.313,-62.279 ; 93.726,-58.293 93.726,-58.42 cw(c93.419,-58.42) 93.636,-58.637 90.56,-61.713 cw(c88.392,-59.545) 89.178,-62.509 ; 94.107,-59.436 ccw(c94.107,-60.356) 93.457,-59.705 91.322,-61.84 cw(c89.154,-59.672) 91.313,-61.849 cw(c89.154,-59.672) 91.177,-61.976 cw(c89.154,-59.672) 90.302,-62.515 ; 94.361,-75.184 115.316,-75.184 cw(c115.316,-78.25) 117.484,-76.082 cw(c115.973,-77.593) 118.11,-77.593 118.11,-84.074 cw(c115.044,-84.074) 117.212,-86.242 115.198,-88.256 cw(c113.03,-86.088) 113.03,-89.154 110.49,-89.154 ; 94.42,-59.758 cw(c97.409,-62.747) 97.409,-58.52 ccw(c97.409,-59.988) 96.371,-58.95 ; 94.615,-7.62 cw(c94.922,-7.927) 94.922,-7.493 95.421,-7.493 cw(c95.421,-9.227) 96.647,-8.001 Q6.1@96.647,-13.335 ; 94.797,-59.381 cw(c96.955,-61.54) C9.2@97.395,-58.519 ; 94.943,-64.135 ccw(c94.943,-63.701) 95.25,-64.008 ; 94.987,-62.747 cw(c97.155,-64.915) 95.607,-62.268 ; 95.123,-62.23 cw(c95.123,-65.296) 95.607,-62.268 ; 95.25,-57.531 94.234,-57.531 ccw(c94.234,-58.801) 92.993,-58.529 ; 95.328,-57.658 cw(c95.328,-60.501) 97.338,-58.491 ccw(c95.635,-60.194) 95.635,-57.785 ; 95.758,-68.326 92.465,-65.033 ccw(c90.297,-67.201) 92.418,-64.987 ; 96.012,-13.081 96.012,-12.954 ccw(c92.946,-12.954) 95.114,-10.786 ccw(c92.99,-12.91) 93.854,-10.033 ; 96.139,-9.652 ccw(c94.299,-11.492) 94.299,-8.89 63.658,-8.89 ccw(c63.658,-10.191) 62.738,-9.271 ccw(c61.512,-10.497) 62.473,-9.054 ; C11.1@96.266,-72.39 cw(c96.266,-75.149) 98.217,-73.198 98.797,-73.778 cw(c96.629,-75.946) 99.695,-75.946 99.695,-80.772 ccw(c102.761,-80.772) 100.593,-82.94 ccw(c102.411,-81.122) 102.411,-83.693 108.331,-83.693 ccw(c108.331,-80.627) 110.499,-82.795 110.608,-82.686 ccw(c108.44,-80.518) 111.506,-80.518 111.506,-74.094 cw(c111.94,-74.094) 111.633,-73.787 115.607,-69.813 ccw(c115.39,-69.596) 115.697,-69.596 113.284,-69.596 cw(c113.284,-66.53) 111.116,-68.698 104.775,-62.357 ; 96.402,-10.931 ccw(c94.234,-13.099) 94.234,-10.033 80.899,-10.033 ccw(c80.899,-13.099) 80.085,-10.143 ; 96.647,-12.442 ccw(c94.51,-12.442) 96.021,-10.931 ccw(c93.853,-13.099) 93.854,-10.033 ; Q6.1@96.774,-13.367 96.774,-11.176 ; 97.028,-13.081 97.028,-8.106 ccw(c96.161,-8.106) 96.774,-7.493 ccw(c96.467,-7.8) 96.467,-7.366 62.865,-7.366 ccw(c62.865,-10.432) 60.697,-8.264 ccw(c62.208,-9.775) 60.071,-9.775 60.071,-31.877 ccw(c60.071,-32.004) 59.944,-32.004 59.944,-37.465 cw(c58.674,-37.465) 59.856,-37.93 ; 97.028,-11.43 103.251,-11.43 cw(c103.251,-14.496) 105.419,-12.328 106.305,-13.214 cw(c104.788,-14.732) 106.934,-14.732 103.251,-14.732 cw(c103.251,-11.666) 101.083,-13.834 99.187,-11.938 99.813,-12.564 ccw(c101.981,-10.396) 101.981,-13.462 105.664,-13.462 104.267,-13.462 cw(c104.267,-10.396) 102.099,-12.564 101.727,-12.192 99.069,-9.534 cw(c101.237,-7.366) 98.171,-7.366 98.171,-6.858 97.911,-6.598 ccw(c96.393,-8.115) 96.393,-5.969 97.4,-6.976 cw(c95.232,-9.144) 98.298,-9.144 98.298,-10.922 ccw(c98.605,-10.615) 98.605,-11.049 107.315,-11.049 ccw(c107.928,-11.662) 107.061,-11.662 107.061,-12.065 ccw(c106.754,-11.758) 107.188,-11.758 ccw(c104.862,-11.758) 106.507,-10.114 104.521,-8.128 ccw(c103.295,-8.128) 104.162,-7.261 103.759,-6.858 103.431,-6.858 cw(c103.431,-6.424) 103.124,-6.731 ccw(c102.817,-7.038) 102.817,-6.604 100.584,-6.604 98.933,-6.604 ccw(c99.24,-6.911) 98.806,-6.911 ccw(c99.599,-6.911) 99.038,-7.471 99.791,-8.224 ccw(c101.092,-6.923) 101.092,-8.763 102.077,-8.763 cw(c102.077,-10.064) 102.997,-9.144 ccw(c104.53,-7.611) 104.53,-9.779 105.537,-9.779 105.097,-9.339 cw(c106.181,-8.255) 104.648,-8.255 103.558,-8.255 cw(c103.558,-7.821) 103.251,-8.128 ccw(c102.944,-8.435) 102.944,-8.001 101.219,-8.001 ccw(c101.219,-8.614) 100.785,-8.181 102.817,-10.213 ccw(c102.997,-10.033) 102.997,-10.287 102.616,-10.287 ccw(c101.696,-11.207) 101.696,-9.906 101.197,-9.906 cw(c101.197,-9.039) 100.584,-9.652 97.79,-9.652 cw(c97.483,-9.345) 97.483,-9.779 105.664,-9.779 cw(c105.664,-12.845) 107.832,-10.677 ; C11.1@97.078,-72.835 ccw(c94.488,-75.01) 94.488,-71.628 ; C11.1@97.155,-72.898 114.173,-72.898 cw(c114.173,-75.964) 116.341,-73.796 117.974,-75.429 cw(c115.806,-77.597) 118.872,-77.597 118.872,-85.313 cw(c117.571,-85.313) 118.491,-86.233 116.288,-88.436 cw(c114.554,-86.701) 114.554,-89.154 114.427,-89.154 ; 97.155,-61.849 ccw(c97.155,-64.915) 95.607,-62.268 ; C11.1@97.226,-72.842 cw(c100.156,-75.772) 100.156,-71.628 ; 97.291,-63.128 ccw(c95.123,-65.296) 95.607,-62.268 ; C9.2@97.315,-58.385 cw(c95.25,-57.612) 95.25,-59.817 ; 97.409,-45.72 103.505,-45.72 103.505,-45.847 ; C9.2@97.48,-58.491 cw(c99.49,-60.501) 99.49,-57.658 ; C9.2@97.536,-57.658 93.98,-57.658 ccw(c93.98,-58.547) 93.097,-58.444 ; 98.044,-59.817 95.25,-59.817 ; C9.2@98.097,-58.039 cw(c98.097,-57.605) 97.79,-57.912 ccw(c97.483,-58.219) 97.483,-57.785 94.996,-57.785 ccw(c94.996,-60.851) 93.097,-58.444 ; 99.314,-72.771 ccw(c96.248,-72.771) 98.416,-70.603 98.171,-70.358 ccw(c98.171,-73.424) 96.003,-71.256 94.615,-72.644 ccw(c95.535,-73.564) 94.234,-73.564 94.234,-81.017 cw(c92.066,-81.017) 93.599,-82.55 cw(c92.066,-81.017) 92.066,-83.185 87.332,-83.185 ccw(c87.332,-83.649) 87.004,-83.321 cw(c89.172,-81.153) 86.106,-81.153 86.106,-70.262 cw(c86.137,-70.262) 86.115,-70.24 ccw(c83.947,-72.408) C14.2@83.947,-69.342 ; 105.791,-4.826 ccw(c108.244,-4.826) 106.509,-6.56 ccw(c106.615,-6.455) 106.615,-6.604 106.627,-6.604 cw(c106.627,-7.038) 106.934,-6.731 ; 105.918,-71.628 94.488,-71.628 ; 110.871,-89.027 cw(c111.178,-89.334) 111.178,-88.9 116.23,-88.9 ccw(c116.23,-86.202) 118.138,-88.11 120.749,-85.499 ccw(c118.841,-83.591) 121.539,-83.591 121.539,-78.994 ; P2.2@112.522,3.048 114.755,3.048 ; P2.2@112.578,2.088 cw(c107.502,-2.988) 114.681,-2.988 ; 112.903,3.302 114.037,3.302 cw(c114.037,1.134) 115.57,2.667 cw(c114.65,1.747) 115.951,1.747 115.951,-45.339 ccw(c119.017,-45.339) 116.849,-47.507 118.872,-49.53 cw(c119.179,-49.53) 118.962,-49.313 ; P2.2@113.03,2.032 114.97,2.032 cw(c114.97,1.196) 115.561,1.787 cw(c113.393,-0.381) 116.459,-0.381 116.459,-36.322 ccw(c119.525,-36.322) 117.357,-38.49 122.292,-43.425 cw(c120.124,-45.593) 123.19,-45.593 123.19,-48.006 ; P2.2@113.086,2.088 cw(c110.156,-0.842) 114.3,-0.842 ; P2.2@113.092,2.083 cw(c109.643,-1.931) 114.935,-1.931 ; P2.2@113.131,2.062 cw(c112.728,0.543) 114.3,0.543 ; 113.157,-44.323 cw(c113.157,-44.63) 113.374,-44.413 114.3,-45.339 ; P2.2@113.246,2.114 cw(c114.755,1.362) 114.755,3.048 ; 113.284,-30.861 113.284,-42.619 ccw(c113.718,-42.619) 113.411,-42.926 ; P2.2@113.284,1.397 113.284,1.524 ccw(c112.237,1.524) 112.977,2.264 112.612,2.63 ccw(c112.829,2.413) 112.522,2.413 112.522,1.778 ccw(c115.588,1.778) 113.42,-0.39 113.538,-0.508 113.538,-28.303 cw(c112.268,-28.303) 113.166,-29.201 ccw(c115.334,-31.369) 112.268,-31.369 112.268,-44.196 ccw(c115.334,-44.196) 113.166,-46.364 114.046,-47.244 cw(c114.046,-50.31) 116.214,-48.142 117.085,-49.013 cw(c114.917,-51.181) 117.983,-51.181 117.983,-51.943 ; C10.2@114.3,-57.531 114.681,-57.531 ccw(c114.681,-54.465) 116.849,-56.633 117.466,-56.016 ccw(c115.298,-53.848) 118.244,-54.696 ; 114.3,-23.114 cw(c112.767,-24.647) 114.427,-23.253 cw(c112.767,-24.647) 114.935,-24.647 114.935,-24.778 ; 114.3,-22.86 114.3,-43.561 ccw(c117.366,-43.561) 115.198,-45.729 117.212,-47.743 cw(c115.044,-49.911) 118.11,-49.911 118.11,-54.229 cw(c115.044,-54.229) 117.212,-56.397 C10.2@115.697,-57.912 ; 114.3,1.016 114.3,-24.892 ccw(c117.366,-24.892) 114.681,-26.372 ccw(c117.366,-24.892) 115.198,-27.06 ; 114.427,-21.336 114.427,-24.384 ccw(c117.493,-24.384) 115.325,-26.552 ; 114.808,2.308 cw(c115.675,2.308) 115.062,2.921 ccw(c114.755,2.614) 114.755,3.048 ; 114.935,2.023 114.935,-23.622 ccw(c118.001,-23.622) 115.833,-25.79 ; 115.316,-30.861 115.316,-37.084 ccw(c118.382,-37.084) 116.214,-39.252 121.92,-44.958 121.92,-54.251 ccw(c122.787,-54.251) 122.174,-54.864 ; 115.443,1.143 115.443,-38.1 ccw(c118.509,-38.1) 116.341,-40.268 122.419,-46.346 122.419,-59.16 ccw(c122.45,-59.16) 122.428,-59.182 ; 115.697,-41.656 ccw(c116.004,-41.656) 115.787,-41.873 121.994,-48.08 cw(c121.561,-48.514) 122.174,-48.514 ; 115.697,-27.178 ccw(c116.004,-27.178) 115.787,-27.395 ; 115.824,-26.924 cw(c115.211,-27.537) 116.032,-27.259 cw(c115.211,-27.537) 116.078,-27.537 ; 116.967,-43.434 116.967,-45.847 ccw(c120.033,-45.847) 117.865,-48.015 118.999,-49.149 ; 117.348,-71.628 118.237,-71.628 cw(c118.237,-74.694) 120.405,-72.526 ; 117.475,-89.281 118.872,-89.281 ccw(c118.872,-86.215) 121.04,-88.383 122.038,-87.385 ccw(c119.87,-85.217) 122.936,-85.217 122.936,-73.025 ; 117.856,-48.79 ccw(c118.723,-48.79) 118.11,-49.403 cw(c116.884,-50.629) 118.237,-49.545 cw(c116.884,-50.629) 118.364,-49.726 cw(c116.884,-50.629) 118.618,-50.629 ; 118.237,-57.785 ccw(c117.93,-58.092) 117.93,-57.658 97.79,-57.658 ccw(c97.79,-60.724) 96.917,-57.785 ccw(c97.79,-60.724) 95.622,-58.556 94.593,-59.585 ccw(c95.46,-60.452) 94.234,-60.452 ccw(c94.234,-61.678) 93.559,-60.655 ; 118.237,-54.483 ccw(c121.303,-54.483) 118.244,-54.696 ; 118.364,-51.943 ccw(c121.43,-51.943) 118.491,-52.816 ccw(c121.43,-51.943) 119.262,-54.111 120.768,-55.617 cw(c118.6,-57.785) 121.539,-56.912 cw(c118.6,-57.785) 121.666,-57.785 121.666,-61.087 ; 118.364,-44.301 118.364,-53.848 cw(c115.298,-53.848) 118.244,-54.696 ; 118.491,-51.562 118.491,-53.213 ccw(c121.557,-53.213) 119.389,-55.381 120.514,-56.506 cw(c118.346,-58.674) 121.412,-58.674 ; 118.618,-50.546 120.641,-52.569 cw(c118.473,-54.737) 121.539,-54.737 121.539,-58.665 cw(c119.371,-58.665) 121.509,-59.025 cw(c119.371,-58.665) 120.904,-60.198 ; 118.872,-46.99 ccw(c121.938,-46.99) 118.999,-47.863 ccw(c121.938,-46.99) 119.253,-48.47 ccw(c121.938,-46.99) 119.77,-49.158 122.038,-51.426 cw(c119.87,-53.594) 122.936,-53.594 ; 118.999,-47.879 ccw(c122.065,-47.879) 119.253,-49.101 ccw(c122.065,-47.879) 119.897,-50.047 122.301,-52.451 cw(c121.075,-53.677) 122.809,-53.677 122.809,-68.58 ; 118.999,-46.482 ccw(c122.065,-46.482) 119.253,-47.704 ccw(c122.065,-46.482) 119.897,-48.65 122.038,-50.791 cw(c119.87,-52.959) 122.936,-52.959 122.936,-59.944 ; 119.253,-53.848 ccw(c122.319,-53.848) 119.265,-54.114 ccw(c122.319,-53.848) 120.151,-56.016 ; 119.507,-71.628 121.666,-73.787 ; 119.634,-52.578 117.357,-54.855 cw(c115.189,-52.687) 115.189,-55.753 87.63,-55.753 ccw(c87.63,-58.819) 85.462,-56.651 85.344,-56.769 cw(c82.278,-56.769) 84.446,-58.937 84.083,-59.3 cw(c81.915,-57.132) 81.915,-60.198 81.915,-69.088 cw(c82.528,-69.701) 82.528,-68.834 ccw(c82.528,-66.022) 84.517,-68.01 87.24,-65.287 cw(c89.408,-67.455) 89.281,-64.392 ; 119.634,-52.197 119.634,-52.451 ccw(c122.7,-52.451) 120.532,-54.619 ; 121.276,-73.397 cw(c119.108,-75.565) 122.174,-75.565 122.174,-76.073 ; 121.666,-59.182 119.135,-56.651 cw(c121.303,-54.483) 118.244,-54.696 ; 122.165,-84.464 ccw(c119.997,-82.296) 123.063,-82.296 123.063,-69.596 ; 122.292,-45.457 cw(c120.124,-47.625) 123.19,-47.625 123.19,-61.722 ; 64.555,-10.828 cw(c66.294,-13.353) 65.216,-10.483 ; 64.978,-10.337 ccw(c65.996,-8.934) 65.163,-10.454 ; 65.163,-10.454 ccw(c65.996,-8.934) 65.216,-10.483 ; 65.163,-10.454 cw(c65.659,-13.48) 65.379,-10.427 ; 65.216,-10.483 cw(c66.294,-13.353) 65.379,-10.427 ; 67.564,-46.609 cw(c68.58,-45.847) 67.31,-45.847 73.787,-45.847 ccw(c73.787,-44.958) 74.422,-45.58 ccw(c73.787,-44.958) 74.571,-45.377 ; 67.564,-46.609 ccw(c68.072,-46.609) 68.072,-47.117 74.676,-47.117 ccw(c74.676,-45.847) 75.791,-46.454 ccw(c74.676,-45.847) 75.912,-46.138 ; 73.152,-66.929 cw(c73.152,-65.703) 72.285,-66.57 cw(c72.951,-67.236) 72.951,-66.294 cw(c72.951,-66.167) 72.861,-66.257 ccw(c73.691,-67.087) 72.517,-67.087 72.517,-70.2 ccw(c73.818,-70.2) 72.898,-71.12 73.062,-71.284 cw(c72.845,-71.501) 73.152,-71.501 73.152,-66.929 ; 74.42,-45.294 cw(c73.025,-48.024) 74.571,-45.377 ; 75.043,-9.999 cw(c73.406,-12.591) 75.096,-10.033 cw(c73.406,-12.591) 75.574,-10.423 76.804,-11.653 cw(c75.503,-12.954) 77.343,-12.954 ccw(c77.956,-12.341) 77.597,-13.13 ccw(c77.956,-12.341) 77.956,-13.208 77.978,-13.208 cw(c80.737,-13.208) 78.786,-11.257 79.366,-10.677 cw(c81.534,-12.845) 80.085,-10.143 ; 75.819,-43.815 cw(c75.819,-45.085) C7.1@76.764,-44.236 ; 75.819,-43.815 cw(c75.819,-45.161) C7.1@76.962,-44.45 ; 75.912,-46.138 cw(c75.63,-47.179) 76.392,-46.417 ccw(c75.017,-45.041) 76.962,-45.041 ccw(c75.228,-45.041) C7.1@76.764,-44.236 ; 76.665,-10.118 cw(c76.064,-12.201) 77.597,-10.668 cw(c77.29,-10.975) 77.724,-10.975 77.798,-10.975 ccw(c77.798,-7.909) 78.582,-10.873 ; 77.65,-47.625 ccw(c77.65,-48.059) 77.343,-47.752 cw(c77.65,-48.059) 77.65,-47.625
